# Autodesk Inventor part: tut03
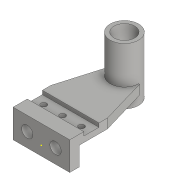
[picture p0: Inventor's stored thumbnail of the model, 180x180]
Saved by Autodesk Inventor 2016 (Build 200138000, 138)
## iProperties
Created: 2015-03
Part Number: tut03
Material: Generic
Document SubType Name: Modeling
Designer: Sandeep
Density: 1 g/cm^3
Appearance: Default
Author: Sandeep
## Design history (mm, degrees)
sketch "Sketch1"
  geometry: L1 (0, 0)-(10, 0); L2 (10, 0)-(10, 20); L3 (10, 20)-(40, 20); L4 (40, 20)-(40, 30); L5 (40, 30)-(31, 30); L6 (31, 30)-(31, 26); L7 (31, 26)-(15, 26); L8 (15, 26)-(15, 30); L9 (15, 30)-(0, 30); L10 (0, 30)-(0, 0)
  constraints: 20 end point, 7 perpendicular, 1 collinear, 1 horizontal, 1 parallel, 1 vertical
  dimensions: "d0" = 10 distance of L1.start L1.end; "d1" = 30 distance of L9.end L1.start; "d2" = 4 distance between parallel lines of L9 L7; "d3" = 15 distance of L8.end L9.end; "d4" = 16 distance of L6.end L7.end; "d5" = 40 distance between parallel lines of L4 L10; "d6" = 10 distance between parallel lines of L5 L3
extrude "Extrusion1" new body sketch "Sketch1" stored distance "d7" = 60; taper "d8" = 0 deg
sketch "Sketch2"
  geometry: L1 (0, 40)-(14, 88); L2 (14, 88)-(46, 88); L3 (0, 40)-(60, 40) reference; L4 (46, 88)-(60, 40); L5 (60, 40)-(0, 40); L6 (30, 0)-(30, 52.82)
  constraints: 11 end point, 1 horizontal, 1 vertical, 1 other
  dimensions: "d9" = 48 distance between parallel lines of L3 L2; "d10" = 32 distance of L1.end L2.end
extrude "Extrusion2" join sketch "Sketch2" distance "d11" = 10; taper "d12" = 0 deg
workplane "Work Plane1"
sketch "Sketch3"
  geometry: 1 further point
sketch "Sketch4"
  geometry: L1 (46, 78)-(14, 78) reference; C1 r 15 at (30, 78); 1 further point
  constraints: 1 centre point, 1 midpoint
  dimensions: "d14" = 30 diameter of C1
extrude "Extrusion3" join sketch "Sketch4" distance "d15" = 60; taper "d16" = 0 deg
sketch "Sketch5"
  geometry: C1 r 11 at (0, 0); C2 r 15 at (0, 0) reference; 1 further point
  constraints: 1 centre point, 1 concentric
  dimensions: "d17" = 22 diameter of C1
extrude "Extrusion4" cut sketch "Sketch5" stored distance "d18" = 0; taper "d19" = 0 deg
sketch "Sketch6"
  geometry: L1 (0.322, 7.5)-(90.552, 7.5); L2 (0, -15)-(60, -15) reference; L3 (0, 0)-(0, 16) reference; C1 r 3 at (10, 7.5); C2 r 3 at (30, 7.5); C3 r 3 at (50, 7.5); 1 further point
  constraints: 3 centre point, 3 point on line, 2 end point, 2 equal radius, 1 horizontal
  dimensions: "d20" = 22.5 distance between parallel lines of L2 L1; "d21" = 6 diameter of C1; "d22" = 10 distance from line of L3 C1.centre; "d23" = 20 distance of C2.centre C1.centre; "d24" = 20 distance of C3.centre C2.centre
extrude "Extrusion5" cut sketch "Sketch6" stored distance "d25" = 60; taper "d26" = 0 deg
sketch "Sketch7"
  geometry: L1 (0, 0)-(0, 30) reference; L2 (0, 15)-(76.431, 15); L3 (60, 30)-(60, 0) reference; C1 r 6 at (15, 15); C2 r 6 at (45, 15); 1 further point
  constraints: 2 centre point, 2 end point, 2 point on line, 1 equal radius, 1 horizontal, 1 midpoint
  dimensions: "d27" = 12 diameter of C2; "d28" = 30 distance of C2.centre C1.centre; "d29" = 15 distance from line of L3 C2.centre
extrude "Extrusion6" cut sketch "Sketch7" distance "d30" = 10; taper "d31" = 0 deg
body "Solid1"
